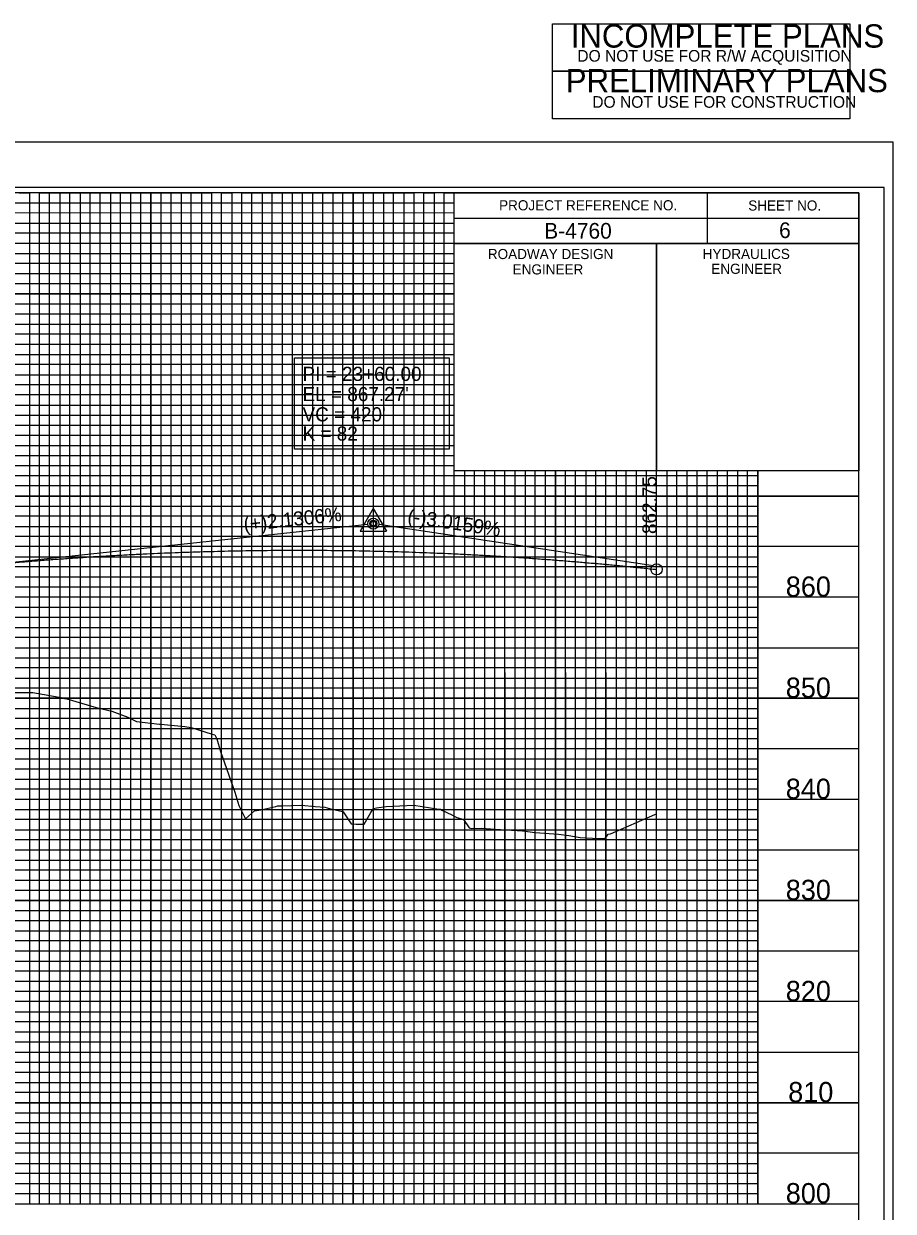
# Model space of a CAD drawing. Extents: x 570622 to 580296, y -55533 to -48575.
# Drawn here: x 571876 to 572306, y -52761 to -52173 of the extents above; entities that cross this region are included whole.
import ezdxf

# ---------------------------------------------------------------- set-up
doc = ezdxf.new("R2010")
doc.units = 0
for name, color, linetype in [('Exist Vertical Profile Ground Line', 7, 'Continuous'), ('Exist Vertical Profile Vertical Axis Label', 7, 'Continuous'), ('Prop Grid Mask', 7, 'Continuous'), ('Prop PFL VPI Symbol CELL', 7, 'Continuous'), ('Prop Vertical Profile Curve Label', 7, 'Continuous'), ('Prop Vertical Profile Grade', 7, 'Continuous'), ('Prop Vertical Profile Grade Label', 7, 'Continuous'), ('Prop VPI Label', 7, 'Continuous'), ('Sheet Cutting Line CELL', 7, 'Continuous'), ('Sheet Data Field CELL', 7, 'Continuous'), ('Sheet DOT Grid CELL', 7, 'Continuous'), ('Sheet Layout Profile Border Port 1', 7, 'Continuous'), ('Sheet Plot Border Inside CELL', 7, 'Continuous'), ('Sheet Plot Border Outside CELL', 7, 'Continuous'), ('Sheet Profile CELL', 7, 'Continuous'), ('Sheet Profile Grid Major CELL', 7, 'Continuous'), ('Sheet Profile Grid Middle CELL', 7, 'Continuous'), ('Sheet Profile Grid Minor CELL', 7, 'Continuous'), ('Sheet Sticker Incomplete CELL', 7, 'Continuous'), ('Sheet Sticker Preliminary CELL', 7, 'Continuous')]:
    doc.layers.add(name, color=color, linetype=linetype)

msp = doc.modelspace()

# ---------------------------------------------------------------- linework, layer by layer
at = {"layer": 'Exist Vertical Profile Ground Line'}
msp.add_lwpolyline([(571871.45, -52504.14), (571880.33, -52504.22), (571883.14, -52504.73), (571893.42, -52506.51), (571895.41, -52506.88), (571896, -52507.09), (571897.11, -52507.38), (571911.67, -52511.56), (571919.46, -52513.46), (571927.33, -52516.45), (571931.66, -52518.6), (571942.96, -52519.78), (571943.62, -52519.87), (571945.31, -52520.09), (571955.57, -52521.05), (571958.67, -52521.46), (571969.08, -52524.8), (571970.36, -52525.14), (571971.31, -52527.17), (571973.09, -52533.4), (571980.15, -52553.5), (571982.13, -52560.11), (571985.53, -52566.61), (571989.98, -52562.69), (571993.09, -52562.22), (572000.44, -52560.52), (572001.38, -52560.29), (572003.22, -52560.22), (572013.21, -52559.89), (572019.89, -52560.53), (572024.77, -52560.97), (572025.86, -52561.29), (572027.5, -52561.78), (572032.86, -52562.95), (572033.74, -52563.21), (572034.1, -52563.64), (572037.66, -52569.06), (572040.18, -52569.23), (572044.13, -52569.28), (572047.45, -52563.59), (572048.7, -52561.53), (572050.17, -52561.23), (572055, -52560.56), (572061.71, -52560.27), (572068.66, -52559.94), (572081.13, -52561.81), (572081.81, -52561.92), (572082.54, -52562.3), (572087.43, -52564.72), (572089.95, -52565.97), (572090.55, -52566.21), (572093.32, -52566.97), (572096.02, -52571.08), (572097.23, -52571.45), (572102.08, -52571.24), (572108.85, -52571.71), (572122.42, -52572.57), (572128.7, -52573.44), (572140.16, -52574.3), (572145.32, -52574.9), (572150.99, -52575.82), (572160.03, -52576.34), (572163.34, -52576.45), (572164.75, -52574.31), (572166, -52574.1), (572187.78, -52564.59), (572188.69, -52564.16)], dxfattribs=at)
at = {"layer": 'Prop Grid Mask'}
msp.add_lwpolyline([(572009.67, -52338.61), (572086.22, -52338.61), (572086.22, -52383.8), (572009.67, -52383.8)], close=True, dxfattribs=at)
at = {"layer": 'Prop PFL VPI Symbol CELL'}
for p, q in [((572048.68, -52413.22), (572042.23, -52424.42)), ((572048.68, -52413.22), (572055.18, -52424.42)), ((572042.23, -52424.42), (572055.18, -52424.42))]:
    msp.add_line(p, q, dxfattribs=at)
for radius in [1.75, 1.2]:
    msp.add_circle((572048.69, -52420.7), radius, dxfattribs=at)
at = {"layer": 'Prop Vertical Profile Grade'}
msp.add_spline([(571838.69, -52443.08), (571845.69, -52442.34), (571852.69, -52441.64), (571859.69, -52440.97), (571866.69, -52440.33), (571873.69, -52439.72), (571880.69, -52439.14), (571887.69, -52438.59), (571894.69, -52438.07), (571901.69, -52437.58), (571908.69, -52437.12), (571915.69, -52436.69), (571922.69, -52436.29), (571929.69, -52435.92), (571936.69, -52435.58), (571943.69, -52435.27), (571950.69, -52434.99), (571957.69, -52434.74), (571964.69, -52434.52), (571971.69, -52434.33), (571978.69, -52434.17), (571985.69, -52434.04), (571992.69, -52433.94), (571999.69, -52433.86), (572006.69, -52433.82), (572013.69, -52433.81), (572020.69, -52433.83), (572027.69, -52433.88), (572034.69, -52433.96), (572041.69, -52434.07), (572048.69, -52434.21), (572055.69, -52434.38), (572062.69, -52434.58), (572069.69, -52434.81), (572076.69, -52435.07), (572083.69, -52435.36), (572090.69, -52435.68), (572097.69, -52436.03), (572104.69, -52436.41), (572111.69, -52436.82), (572118.69, -52437.26), (572125.69, -52437.73), (572132.69, -52438.23), (572139.69, -52438.76), (572146.69, -52439.33), (572153.69, -52439.92), (572160.69, -52440.54), (572167.69, -52441.19), (572174.69, -52441.87), (572181.69, -52442.58), (572188.69, -52443.32)], degree=3, dxfattribs=at)
at = {"layer": 'Prop VPI Label'}
for p, q in [((571838.69, -52443.08), (572045.95, -52421)), ((572185.97, -52441.41), (572051.41, -52421.11))]:
    msp.add_line(p, q, dxfattribs=at)
for centre in [(572048.69, -52420.7), (572188.69, -52443.32)]:
    msp.add_circle(centre, 2.75, dxfattribs=at)
at = {"layer": 'Sheet Cutting Line CELL'}
msp.add_line((572305.69, -52232.05), (570621.69, -52232.05), dxfattribs=at)
at = {"layer": 'Sheet DOT Grid CELL'}
for p, q in [((571888.69, -52757.05), (571888.69, -52257.05)), ((571938.69, -52757.05), (571938.69, -52257.05)), ((571988.69, -52757.05), (571988.69, -52257.05)), ((572038.69, -52757.05), (572038.69, -52257.05)), ((572088.64, -52307.05), (570788.69, -52307.05)), ((572088.64, -52357.05), (570788.69, -52357.05)), ((572088.69, -52757.05), (572088.69, -52394.6)), ((572138.69, -52757.05), (572138.69, -52394.6)), ((572188.69, -52757.05), (572188.69, -52394.6)), ((572238.69, -52757.05), (572238.69, -52394.6)), ((572288.69, -52407.05), (570788.69, -52407.05)), ((572288.69, -52457.05), (570788.69, -52457.05)), ((572288.69, -52507.05), (570788.69, -52507.05)), ((572288.69, -52557.05), (570788.69, -52557.05)), ((572288.69, -52607.05), (570788.69, -52607.05)), ((572288.69, -52657.05), (570788.69, -52657.05)), ((572288.69, -52707.05), (570788.69, -52707.05))]:
    msp.add_line(p, q, dxfattribs=at)
at = {"layer": 'Sheet Layout Profile Border Port 1'}
msp.add_lwpolyline([(570838.69, -52257.05), (570838.69, -52757.05), (572238.69, -52757.05), (572238.69, -52394.6), (572088.64, -52394.6), (572088.64, -52257.05)], close=True, dxfattribs=at)
at = {"layer": 'Sheet Plot Border Inside CELL'}
msp.add_lwpolyline([(570634.69, -53309.6), (572301.19, -53309.6), (572301.19, -52254.5), (570634.69, -52254.5)], close=True, dxfattribs=at)
at = {"layer": 'Sheet Plot Border Outside CELL'}
msp.add_lwpolyline([(570621.69, -53332.05), (572305.69, -53332.05), (572305.69, -52232.05), (570621.69, -52232.05)], close=True, dxfattribs=at)
at = {"layer": 'Sheet Profile CELL'}
for p, q in [((572213.69, -52257.1), (572213.69, -52282.1)), ((572088.64, -52269.6), (572288.69, -52269.6)), ((572188.69, -52282.1), (572188.69, -52394.55)), ((570788.69, -52757.05), (572288.69, -52757.05))]:
    msp.add_line(p, q, dxfattribs=at)
for points in [[(572288.69, -52257.05), (570788.69, -52257.05), (570788.69, -53307.05), (572288.69, -53307.05)], [(572088.64, -52257.05), (572288.69, -52257.05), (572288.69, -52282.1), (572088.64, -52282.1)], [(572088.64, -52282.1), (572188.69, -52282.1), (572188.69, -52394.6), (572088.64, -52394.6)], [(572188.69, -52282.1), (572288.69, -52282.1), (572288.69, -52394.6), (572188.69, -52394.6)]]:
    msp.add_lwpolyline(points, close=True, dxfattribs=at)
at = {"layer": 'Sheet Profile Grid Major CELL'}
for points in [[(571838.69, -52757.05), (571888.69, -52757.05), (571888.69, -52257.05), (571938.69, -52257.05), (571938.69, -52757.05), (571988.69, -52757.05), (571988.69, -52257.05), (572038.69, -52257.05), (572038.69, -52757.05), (572088.69, -52757.05), (572088.69, -52257.05), (572114.99, -52257.05)], [(570788.69, -52307.05), (572088.69, -52307.05)], [(572088.69, -52357.05), (570788.69, -52357.05), (570788.69, -52407.05), (572288.69, -52407.05)], [(572138.69, -52394.6), (572138.69, -52757.05), (572188.69, -52757.05), (572188.69, -52757.05), (572188.69, -52394.6)], [(572238.69, -52394.6), (572238.69, -52757.05), (572288.69, -52757.05), (572288.69, -52407.05)], [(572288.69, -52457.05), (570788.69, -52457.05), (570788.69, -52507.05), (572288.69, -52507.05)], [(572288.69, -52557.05), (570788.69, -52557.05), (570788.69, -52607.05), (572288.69, -52607.05)], [(572288.69, -52657.05), (570788.69, -52657.05), (570788.69, -52657.05), (570788.69, -52707.05), (572288.69, -52707.05)]]:
    msp.add_lwpolyline(points, dxfattribs=at)
at = {"layer": 'Sheet Profile Grid Middle CELL'}
msp.add_line((570788.69, -52282.05), (572088.64, -52282.05), dxfattribs=at)
for points in [[(571863.69, -52757.05), (571913.69, -52757.05), (571913.69, -52257.05), (571963.69, -52257.05), (571963.69, -52757.05), (572013.69, -52757.05), (572013.69, -52257.05), (572063.69, -52257.05), (572063.69, -52757.05), (572113.69, -52757.05), (572113.69, -52394.6)], [(572088.69, -52332.05), (570788.69, -52332.05), (570788.69, -52382.05), (572088.69, -52382.05)], [(572113.69, -52494.25), (572113.69, -52757.05), (572163.69, -52757.05), (572163.69, -52394.6)], [(572163.69, -52494.25), (572163.69, -52757.05), (572213.69, -52757.05), (572213.69, -52394.6)], [(572288.69, -52432.05), (570788.69, -52432.05), (570788.69, -52482.05), (572113.69, -52482.05)], [(572113.69, -52482.05), (572288.69, -52482.05)], [(572288.69, -52532.05), (570788.69, -52532.05), (570788.69, -52582.05), (572288.69, -52582.05)], [(572288.69, -52632.05), (570788.69, -52632.05), (570788.69, -52682.05), (572288.69, -52682.05)], [(572288.69, -52732.05), (570788.69, -52732.05)]]:
    msp.add_lwpolyline(points, dxfattribs=at)
at = {"layer": 'Sheet Profile Grid Minor CELL'}
for p, q in [((570838.69, -52262.05), (572088.69, -52262.05)), ((572088.69, -52267.05), (570838.69, -52267.4)), ((570838.69, -52272.05), (572088.69, -52272.05)), ((572088.64, -52392.05), (570838.69, -52392.05)), ((572238.69, -52397.05), (570838.69, -52397.05)), ((572238.69, -52402.05), (570838.69, -52402.05)), ((570838.69, -52412.05), (572238.69, -52412.05)), ((572238.69, -52417.05), (570838.69, -52417.05)), ((570838.69, -52422.05), (572238.69, -52422.05)), ((572238.69, -52442.05), (570838.69, -52442.05)), ((570838.69, -52447.05), (572238.69, -52447.05)), ((572238.69, -52467.05), (570838.69, -52467.05)), ((570838.69, -52472.05), (572238.69, -52472.05)), ((572238.69, -52492.05), (570838.69, -52492.05)), ((570838.69, -52497.05), (572238.69, -52497.05)), ((572238.69, -52502.05), (570838.69, -52502.05)), ((570838.69, -52512.05), (572238.69, -52512.05)), ((572238.69, -52517.05), (570838.69, -52517.05)), ((570838.69, -52522.05), (572238.69, -52522.05)), ((572238.69, -52527.05), (570838.69, -52527.05)), ((570838.69, -52537.05), (572238.69, -52537.05)), ((572238.69, -52542.05), (570838.69, -52542.05)), ((570838.69, -52547.05), (572238.69, -52547.05)), ((572238.69, -52552.05), (570838.69, -52552.05)), ((570838.69, -52562.05), (572238.69, -52562.05)), ((572238.69, -52567.05), (570838.69, -52567.05)), ((570838.69, -52572.05), (572238.69, -52572.05)), ((572238.69, -52577.05), (570838.69, -52577.05)), ((570838.69, -52587.05), (572238.69, -52587.05)), ((572238.69, -52592.05), (570838.69, -52592.05)), ((570838.69, -52597.05), (572238.69, -52597.05)), ((572238.69, -52602.05), (570838.69, -52602.05)), ((570838.69, -52612.05), (572238.69, -52612.05)), ((572238.69, -52617.05), (570838.69, -52617.05)), ((570838.69, -52622.05), (572238.69, -52622.05)), ((572238.69, -52627.05), (570838.69, -52627.05)), ((570838.69, -52637.05), (572238.69, -52637.05)), ((572238.69, -52642.05), (570838.69, -52642.05)), ((572238.69, -52647.05), (570838.69, -52647.05)), ((572238.69, -52652.05), (570838.69, -52652.05)), ((570838.69, -52662.05), (572238.69, -52662.05)), ((572238.69, -52667.05), (570838.69, -52667.05)), ((570838.69, -52672.05), (572238.69, -52672.05)), ((572238.69, -52677.05), (570838.69, -52677.05)), ((570838.69, -52687.05), (572238.69, -52687.05)), ((572238.69, -52692.05), (570838.69, -52692.05)), ((570838.69, -52697.05), (572238.69, -52697.05)), ((572238.69, -52702.05), (570838.69, -52702.05)), ((570838.69, -52712.05), (572238.69, -52712.05)), ((572238.69, -52717.05), (570838.69, -52717.05)), ((570838.69, -52722.05), (572238.69, -52722.05)), ((572238.69, -52727.05), (570838.69, -52727.05)), ((570838.69, -52737.05), (572238.69, -52737.05)), ((572238.69, -52742.05), (570838.69, -52742.05)), ((570838.69, -52747.05), (572238.69, -52747.05))]:
    msp.add_line(p, q, dxfattribs=at)
for points in [[(571873.69, -52257.05), (571878.69, -52257.05), (571878.69, -52757.05), (571883.69, -52757.05), (571883.69, -52257.05), (571893.69, -52257.05), (571893.69, -52757.05), (571898.69, -52757.05), (571898.69, -52257.05), (571903.69, -52257.05), (571903.69, -52757.05), (571908.69, -52757.05), (571908.69, -52257.05), (571918.69, -52257.05), (571918.69, -52757.05), (571923.69, -52757.05), (571923.69, -52257.05), (571928.69, -52257.05), (571928.69, -52757.05), (571933.69, -52757.05), (571933.69, -52257.05), (571943.69, -52257.05), (571943.69, -52757.05), (571948.69, -52757.05), (571948.69, -52257.05), (571953.69, -52257.05), (571953.69, -52757.05), (571958.69, -52757.05), (571958.69, -52257.05), (571968.69, -52257.05), (571968.69, -52757.05), (571973.69, -52757.05), (571973.69, -52257.05), (571978.69, -52257.05), (571978.69, -52757.05)], [(571978.69, -52757.05), (571983.69, -52757.05), (571983.69, -52257.05), (571993.69, -52257.05), (571993.69, -52757.05), (571998.69, -52757.05), (571998.69, -52257.05), (572003.69, -52257.05), (572003.69, -52757.05), (572008.69, -52757.05), (572008.69, -52257.05), (572018.69, -52257.05), (572018.69, -52757.05), (572023.69, -52757.05), (572023.69, -52257.05), (572028.69, -52257.05), (572028.69, -52757.05), (572033.69, -52757.05), (572033.69, -52257.05), (572043.69, -52257.05), (572043.69, -52757.05), (572048.69, -52757.05), (572048.69, -52257.05), (572053.69, -52257.05), (572053.69, -52757.05), (572058.69, -52757.05), (572058.69, -52257.05), (572068.69, -52257.05), (572068.69, -52757.05), (572073.69, -52757.05), (572073.69, -52257.05), (572078.69, -52257.05), (572078.69, -52757.05), (572083.69, -52757.05), (572083.69, -52257.05), (572093.69, -52257.05)], [(572088.69, -52277.05), (570838.69, -52277.05), (570838.69, -52287.05), (572088.69, -52287.05)], [(572088.64, -52292.05), (570838.69, -52292.05), (570838.69, -52297.05), (572088.69, -52297.05)], [(572088.69, -52302.05), (570838.69, -52302.05), (570838.69, -52312.05), (572088.69, -52312.05)], [(572088.69, -52317.05), (570838.69, -52317.05), (570838.69, -52322.05), (572088.69, -52322.05)], [(572088.69, -52327.05), (570838.69, -52327.05), (570838.69, -52337.05), (572088.69, -52337.05)], [(572088.69, -52342.05), (570838.69, -52342.05), (570838.69, -52347.05), (572088.69, -52347.05)], [(572088.69, -52352.05), (570838.69, -52352.05), (570838.69, -52362.05), (572088.69, -52362.05)], [(572088.69, -52367.15), (570838.79, -52367.15), (570838.79, -52372.05), (572088.69, -52372.05)], [(572088.69, -52377.05), (570838.69, -52377.05), (570838.69, -52387.05), (572088.69, -52387.05)], [(572093.69, -52394.6), (572093.69, -52757.05), (572098.69, -52757.05), (572098.69, -52394.6)], [(572103.69, -52394.6), (572103.69, -52757.05), (572108.69, -52757.05), (572108.69, -52394.6)], [(572118.69, -52394.6), (572118.69, -52757.05), (572118.69, -52757.05), (572123.69, -52757.05), (572128.69, -52757.05), (572128.69, -52394.6)], [(572123.69, -52394.6), (572123.69, -52757.05)], [(572133.69, -52394.6), (572133.59, -52757), (572138.59, -52757), (572143.69, -52757.05), (572143.69, -52394.6)], [(572143.69, -52494.25), (572143.69, -52757.05), (572148.69, -52757.05), (572148.69, -52394.6)], [(572153.69, -52394.6), (572153.69, -52757.05), (572158.69, -52757.05), (572158.69, -52394.6)], [(572168.69, -52394.6), (572168.69, -52757.05), (572173.69, -52757.05), (572173.69, -52394.6)], [(572178.69, -52394.6), (572178.69, -52757.05), (572183.69, -52757.05), (572183.69, -52394.6)], [(572193.69, -52394.6), (572193.69, -52757.05), (572198.69, -52757.05), (572198.69, -52394.6)], [(572203.69, -52394.6), (572203.69, -52757.05), (572208.69, -52757.05), (572208.69, -52394.6)], [(572218.69, -52394.6), (572218.69, -52757.05), (572223.69, -52757.05), (572223.69, -52394.6)], [(572228.69, -52394.6), (572228.69, -52757.05), (572233.69, -52757.05), (572233.69, -52394.6)], [(572238.69, -52427.05), (570838.69, -52427.05), (570838.69, -52437.05), (572238.69, -52437.05)], [(572238.69, -52452.05), (570838.69, -52452.05), (570838.69, -52462.05), (572238.69, -52462.05)], [(572238.69, -52477.05), (570838.69, -52477.05), (570838.69, -52487.05), (572238.69, -52487.05)], [(572238.69, -52752.05), (570838.69, -52752.05)]]:
    msp.add_lwpolyline(points, dxfattribs=at)
at = {"layer": 'Sheet Sticker Incomplete CELL'}
msp.add_lwpolyline([(572137.31, -52196.96), (572137.31, -52173.46), (572284.31, -52173.46), (572284.31, -52196.96)], close=True, dxfattribs=at)
at = {"layer": 'Sheet Sticker Preliminary CELL'}
msp.add_lwpolyline([(572137.31, -52220.46), (572137.31, -52196.96), (572284.31, -52196.96), (572284.31, -52220.46)], close=True, dxfattribs=at)

# ---------------------------------------------------------------- texts
at = {"layer": 'Exist Vertical Profile Vertical Axis Label'}
for s, p in [('860', (572252.56, -52456.8)), ('850', (572252.56, -52506.8)), ('840', (572252.56, -52556.8)), ('830', (572252.56, -52606.8)), ('820', (572252.56, -52656.8)), ('810', (572253.76, -52706.8)), ('800', (572252.56, -52756.8))]:
    msp.add_text(s, height=10, dxfattribs=at).set_placement(p)
at = {"layer": 'Prop Vertical Profile Curve Label'}
for s, p in [("VC = 420'", (572013.69, -52370.11)), ('K = 82', (572013.69, -52379.6))]:
    msp.add_text(s, height=7, dxfattribs=at).set_placement(p)
at = {"layer": 'Prop Vertical Profile Grade Label'}
for s, rotation, p in [('(+)2.1306%', 6.08066, (571984.92, -52424.48)), ('(-)3.0159%', 351.42467, (572065.26, -52420.17))]:
    msp.add_text(s, height=7, rotation=rotation, dxfattribs=at).set_placement(p)
at = {"layer": 'Prop VPI Label'}
for s, p in [('PI = 23+60.00', (572013.69, -52350.11)), ("EL = 867.27'", (572013.69, -52360.11))]:
    msp.add_text(s, height=7, dxfattribs=at).set_placement(p)
msp.add_text('862.75', height=7, rotation=90, dxfattribs=at).set_placement((572188.69, -52425.82))
at = {"layer": 'Sheet Data Field CELL'}
for s, p in [('B-4760', (572133.14, -52279.74)), ('6', (572249.25, -52279.44))]:
    msp.add_text(s, height=7.75, dxfattribs=at).set_placement(p)
at = {"layer": 'Sheet Profile CELL'}
for s, height, p in [('PROJECT REFERENCE NO.', 5.0001, (572110.85, -52265.74)), ('SHEET NO.', 5, (572234, -52265.84)), ('ROADWAY DESIGN', 5.0001, (572105.3, -52289.84)), ('HYDRAULICS', 5, (572211.5, -52289.79)), ('ENGINEER', 5, (572117.55, -52297.44)), ('ENGINEER', 5, (572215.75, -52297.14))]:
    msp.add_text(s, height=height, dxfattribs=at).set_placement(p)
at = {"layer": 'Sheet Sticker Incomplete CELL'}
for s, height, p in [('INCOMPLETE PLANS', 11.52, (572146.26, -52185.26)), ('DO NOT USE FOR R/W ACQUISITION', 5.76, (572149.51, -52192.21))]:
    msp.add_text(s, height=height, dxfattribs=at).set_placement(p)
at = {"layer": 'Sheet Sticker Preliminary CELL'}
for s, height, p in [('PRELIMINARY PLANS', 11.52, (572143.81, -52207.31)), ('DO NOT USE FOR CONSTRUCTION', 5.76, (572156.91, -52215.01))]:
    msp.add_text(s, height=height, dxfattribs=at).set_placement(p)

doc.saveas('drawing.dxf')
